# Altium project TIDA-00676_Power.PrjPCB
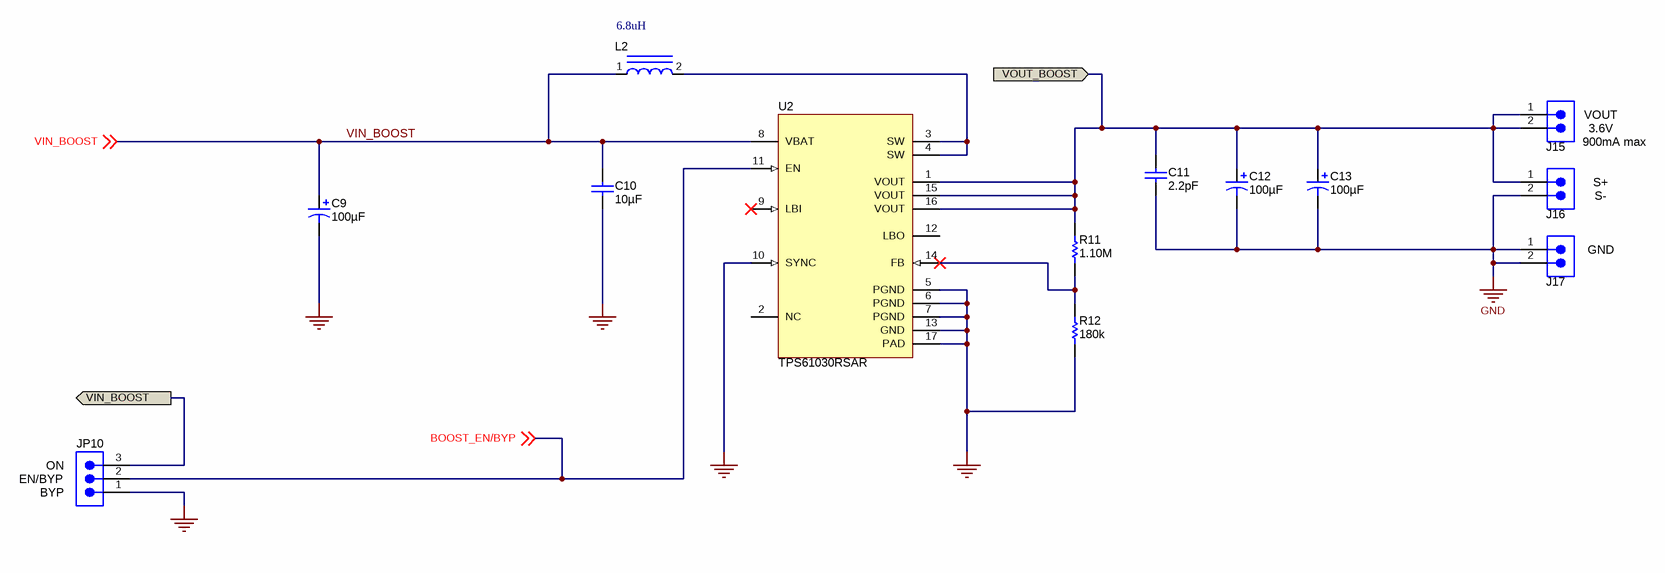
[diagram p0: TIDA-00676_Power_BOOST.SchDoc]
CopyrightYear: 2015; PCB_Layout: Fred Illguth; PCB_Rev: E1; PRJ_Customer: Public Release; PRJ_Engineer: Florian Feckl; PRJ_Number: ALPS-0199; PRJ_Title: TIDA-00676; SCH_Rev: E1; TechSupport: http://www.ti.com/support
3 sheets, 89 parts. Net scope: flat (ports and power ports of the same name join across sheets).
Board file: TIDA-00676_Power.PcbDoc
Sheets:
  TIDA-00676_Power_BOOST.SchDoc
  TIDA-00676_Power_BUCK.SchDoc
  TIDA-00676_Power_Hardware.SchDoc

## Sheet TIDA-00676_Power_BOOST.SchDoc
size 431 x 279 mm; Date: Not shown in title block; ApprovedBy: Not shown in title block; CheckedBy: Not shown in title block; Author: Not shown in title block; CompanyName: Not shown in title block; Engineer: Not shown in title block; Organization: Not shown in title block; Address1: Not shown in title block; Address2: Not shown in title block; Address3: Not shown in title block; Address4: Not shown in title block; DocumentNumber: 1; Revision: Use project parameter SCH_Rev; SheetNumber: 1; SheetTotal: 1; PageSetup: Record=PageOptions|CenterHorizontal=True|CenterVertical=True|PrintScale=1.00|XCorrection=1.00|YCorrection=1.00|PrintKind=0|BorderSize=5000000|LeftOffset=0|BottomOffset=0|Orientation=2|PaperLength=1000|PaperWidth=1000|Scale=100|PaperSource=15|PrintQuality=600|MediaType=1|DitherType=10|PaperKind=Letter|PrintScaleMode=1

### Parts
C9  ValueDisplayed: 100µF  [CC_CASED]  (hidden comment: 594D107X0016D2T)
C10  ValueDisplayed: 10µF  [1206]  (hidden comment: C3216X5R0J106M)
C11  ValueDisplayed: 2.2pF  [0805_HV]  (hidden comment: 08055A2R2CAT2A)
C12  ValueDisplayed: 100µF  [CC_CASED]  (hidden comment: 594D107X0016D2T)
C13  ValueDisplayed: 100µF  [CC_CASED]  (hidden comment: 594D107X0016D2T)
J15  TSW-102-07-G-S  [TSW-102-07-G-S]  (value not drawn)
J16  TSW-102-07-G-S  [TSW-102-07-G-S]  (value not drawn)
J17  TSW-102-07-G-S  [TSW-102-07-G-S]  (value not drawn)
JP10  TSW-103-07-G-S  [TSW-103-07-G-S]  (value not drawn)
L2  value 6.8uH  [IND_CDRH124]  (hidden comment: CDRH124-6R8)
R11  ValueDisplayed: 1.10M  [0603]  (hidden comment: CRCW06031M10FKEA)
R12  ValueDisplayed: 180k  [0603]  (hidden comment: CRCW0603180KJNEA)
U2  TPS61030RSAR  [RSA0016B]

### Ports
VIN_BOOST, VOUT_BOOST

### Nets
GND: C9.2(-) C10.2 C11.2 C12.2(-) C13.2(-) J16.2 J17.1 J17.2 JP10.1 R12.1 U2.5(PGND) U2.6(PGND) U2.7(PGND) U2.10(SYNC) U2.13(GND) U2.17(PAD)
BOOST_EN/BYP: JP10.2 U2.11(EN) ; off-sheet BOOST_EN/BYP
VIN_BOOST: JP10.3 ; port VIN_BOOST
VIN_BOOST: C9.1(+) C10.1 L2.1 U2.8(VBAT) ; off-sheet VIN_BOOST  [a separate net that carries the same name]
VOUT_BOOST: C11.1 C12.1(+) C13.1(+) J15.1 J15.2 J16.1 R11.2 U2.1(VOUT) U2.15(VOUT) U2.16(VOUT) ; port VOUT_BOOST
NetL2_2: L2.2 U2.3(SW) U2.4(SW)
NetR11_1: R11.1 R12.2 U2.14(FB)

Not connected (* = marked no-connect by the designer): U2 2(NC) 9(LBI)* 12(LBO)

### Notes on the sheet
- (near J15) VOUT
- 3.6V
- 900mA max
- S+
- S-
- GND
- (near JP10) EN/BYP
- (near JP10) BYP
- (near JP10) ON

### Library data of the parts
C9 C12 C13 = 594D107X0016D2T: CAP, TA, 100 µF, 16 V, +/- 20%, 0.09 ohm, SMD; Manufacturer: Vishay-Sprague; Polarized: Y; CompType: Capacitor; Value: 100uF; U/M: EA; Cap_F: 0.0001; Tolerance_%: 20; VDC_V: 16; Value2: 16V; ESR_ohm: 0.09; IRMS_A: 1.3; TaMin_C: -55; TaMax_C: 85; Cap_Case: D
C10 = C3216X5R0J106M: CAP, CERM, 10 µF, 6.3 V, +/- 20%, X5R, 1206; Manufacturer: TDK; Polarized: N; CompType: Capacitor; Value: 10uF; U/M: EA; Cap_F: 0.00001; Tolerance_%: 20; ESR_ohm: 0.0031; Value1: 0.0031 ohm; VDC_V: 6.3; Value2: 6.3V; IRMS_A: 4.1; TaMin_C: -55; TaMax_C: 85
C11 = 08055A2R2CAT2A: CAP, CERM, 2.2 pF, 50 V, +/- 11%, C0G/NP0, 0805; Manufacturer: AVX; Polarized: N; CompType: Capacitor; Value: 2.2pF; U/M: EA; Cap_F: 0.0000000000022; Tolerance_%: 11; ESR_ohm: 4.726; Value1: 4.726 ohm; VDC_V: 50; Value2: 50V; TaMin_C: -55; TaMax_C: 125; Cap_Case: 0805
J15-J17 = TSW-102-07-G-S: Header, TH, 100mil, 2x1, Gold plated, 230 mil above insulator; Manufacturer: Samtec, Inc.; SymbolCreator: a0412235; U/M: EA
JP10 = TSW-103-07-G-S: Header, TH, 100mil, 3x1, Gold plated, 230 mil above insulator; Manufacturer: Samtec, Inc.; SymbolCreator: a0799628; U/M: EA
L2 = IND_CDRH124_SERIES: Inductor, SMT, yyA, zzmilliohm; Manufacturer: Sumida; Area: 95275
R11 = CRCW06031M10FKEA: RES, 1.10 M, 1%, 0.1 W, 0603; Manufacturer: Vishay-Dale; CompType: Resistor; Value: 1.10Meg; Res_ohm: 1100000; Value_Code: 1M10; Tolerance_%: 1; Power_W: 0.1; Value2: 0.1W; VDC_V: 75; TempCo: 100 ppm/C; EIA_Code: E96; U/M: EA
R12 = CRCW0603180KJNEA: RES, 180 k, 5%, 0.1 W, 0603; Manufacturer: Vishay-Dale; CompType: Resistor; Value: 180k; Res_ohm: 180000; Tolerance_%: 5; Power_W: 0.1; Value2: 0.1W; VDC_V: 75; TempCo: 200 ppm/C; EIA_Code: E24; U/M: EA
U2 = TPS61030RSAR: 96% Efficient Synchronous Boost Converter With 4A Switch, RSA0016B; Manufacturer: Texas Instruments; SymbolCreator: Altium; CompType: IC; U/M: EA

## Sheet TIDA-00676_Power_BUCK.SchDoc
size 431 x 279 mm; Date: Not shown in title block; ApprovedBy: Not shown in title block; CheckedBy: Not shown in title block; Author: Not shown in title block; CompanyName: Not shown in title block; Engineer: Not shown in title block; Organization: Not shown in title block; Address1: Not shown in title block; Address2: Not shown in title block; Address3: Not shown in title block; Address4: Not shown in title block; DocumentNumber: 1; Revision: Use project parameter SCH_Rev; SheetNumber: 1; SheetTotal: 2; PageSetup: Record=PageOptions¦CenterHorizontal=True¦CenterVertical=True¦PrintScale=0.62¦XCorrection=1.00¦YCorrection=1.00¦PrintKind=0¦BorderSize=5000000¦LeftOffset=0¦BottomOffset=0¦Orientation=2¦PaperLength=1000¦PaperWidth=1000¦Scale=100¦PaperSource=15¦PrintQuality=600¦MediaType=1¦DitherType=10¦PaperKind=Letter¦PrintScaleMode=1
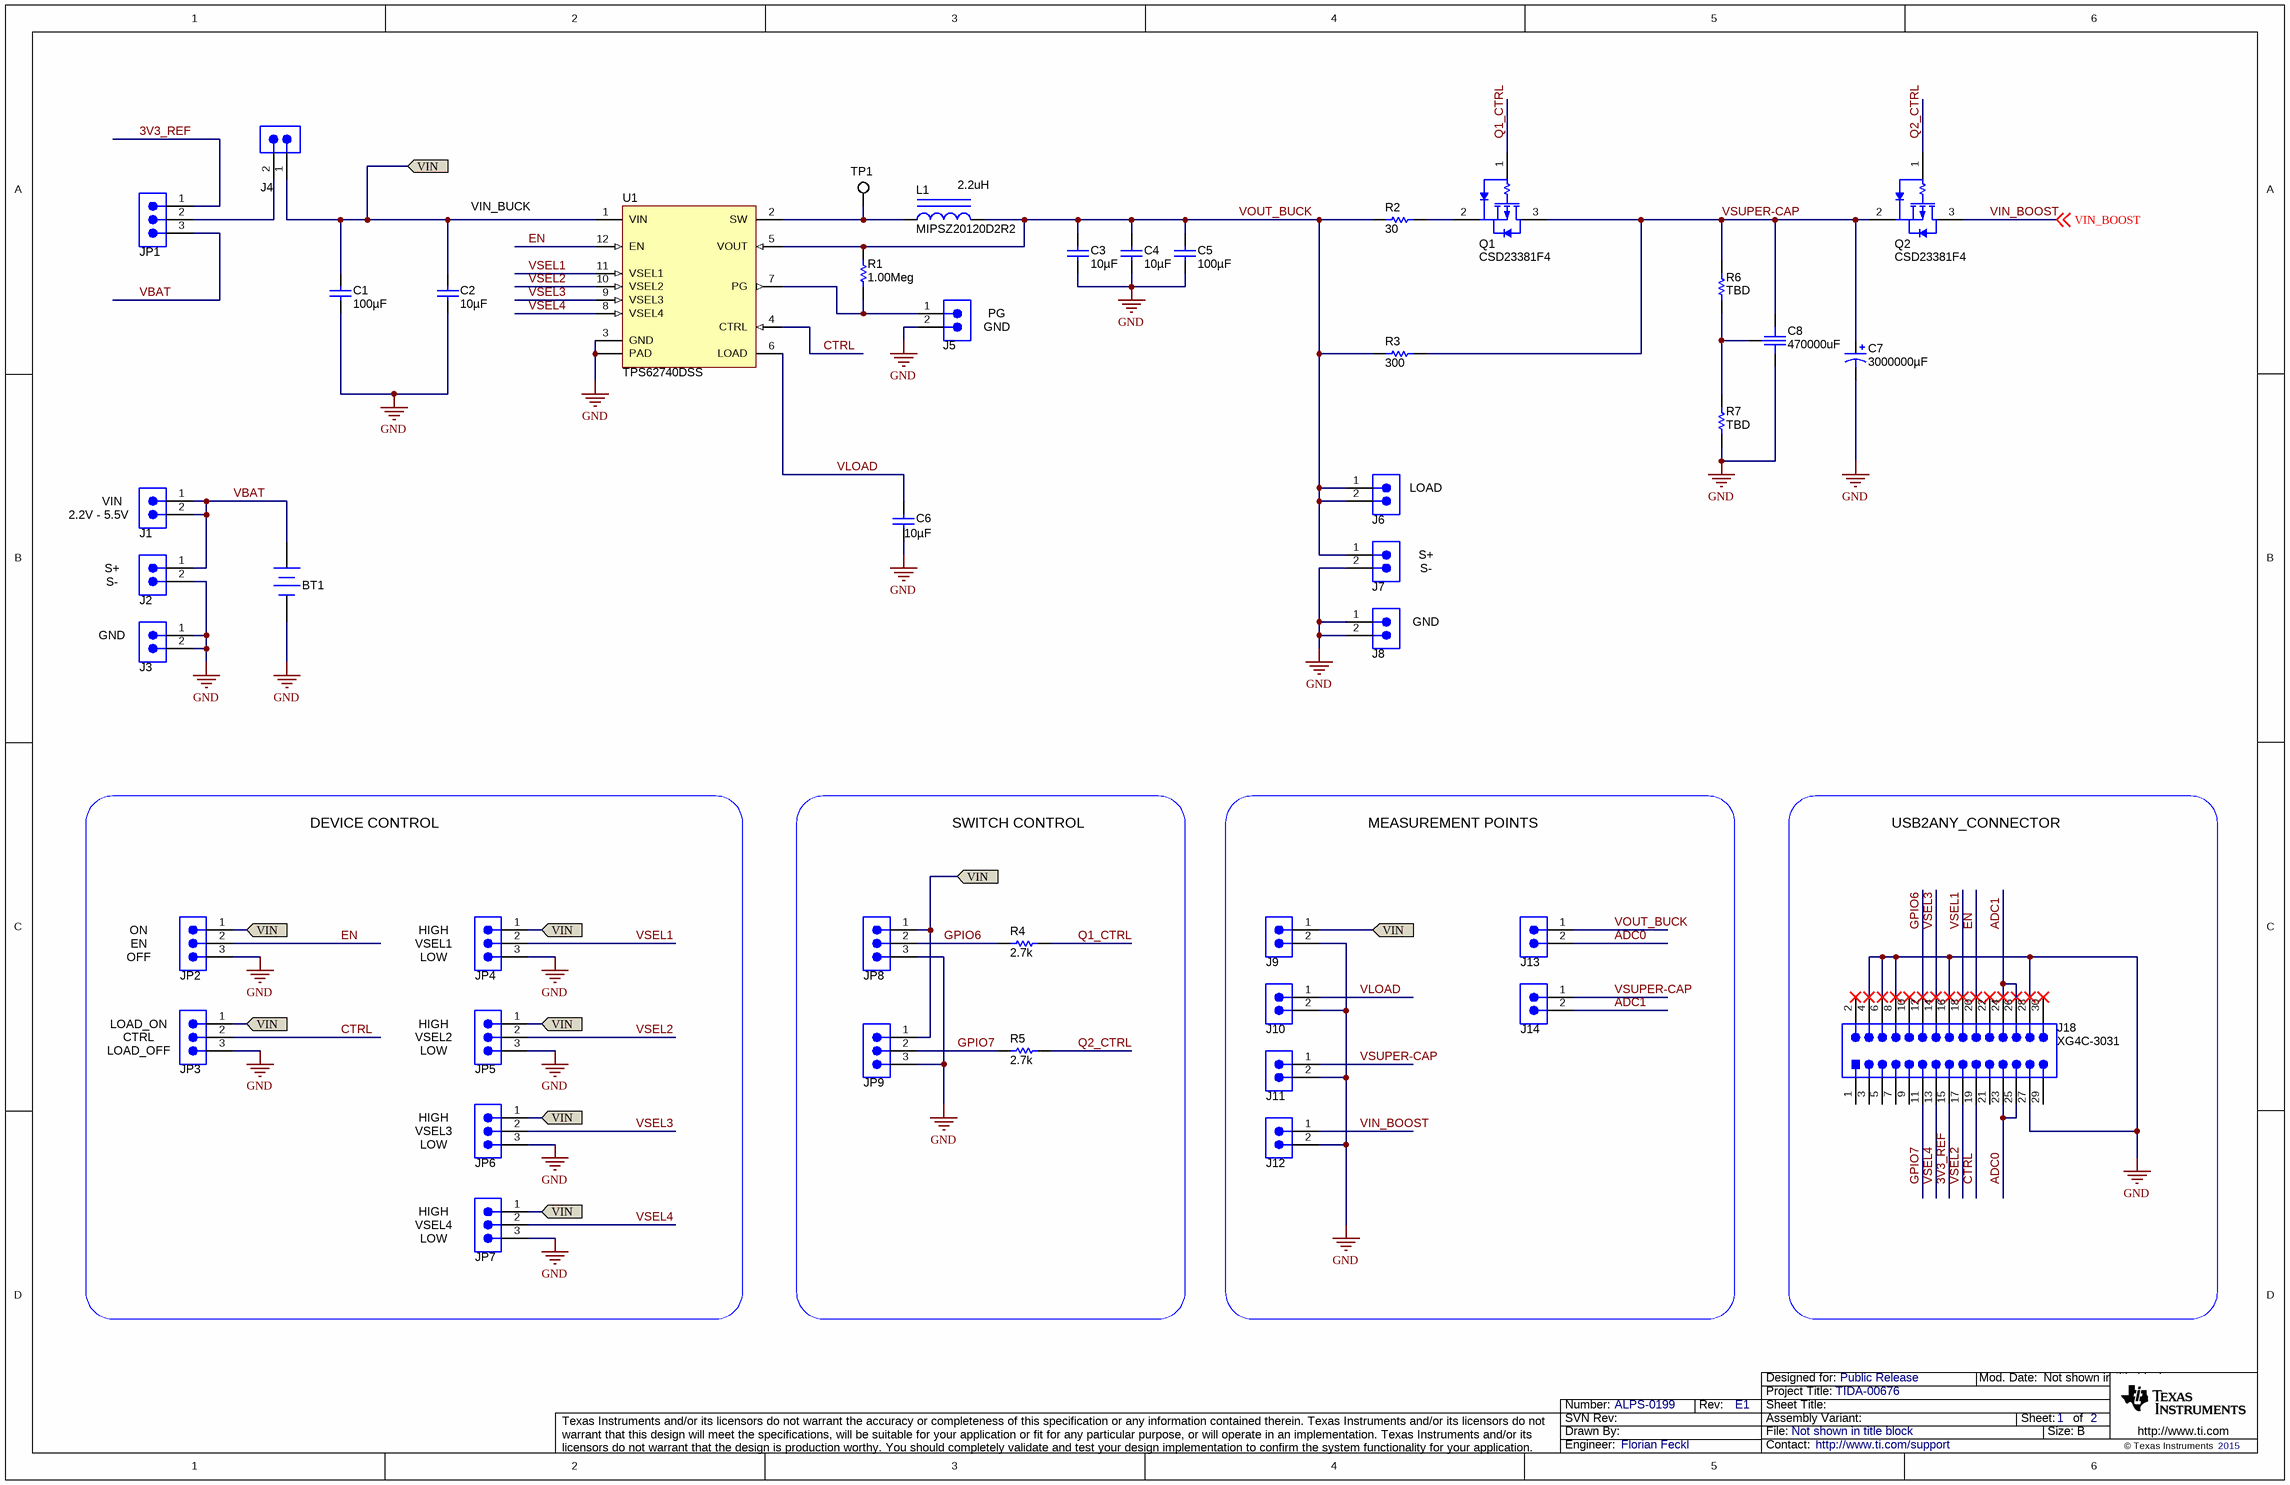
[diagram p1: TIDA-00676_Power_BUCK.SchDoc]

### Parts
BT1  SL360/P  [Tadiran_SL360-P]  (value not drawn)
C1  ValueDisplayed: 100µF  [1210]  (hidden comment: GRM32ER60J107ME20L)
C2  ValueDisplayed: 10µF  [0603_HV]  (hidden comment: GRM188R60J106ME84)
C3  ValueDisplayed: 10µF  [0603_HV]  (hidden comment: GRM188R60J106ME84)
C4  ValueDisplayed: 10µF  [0603]  (hidden comment: GRM188R60J106ME84)
C5  ValueDisplayed: 100µF  [1210]  (hidden comment: GRM32ER60J107ME20L)
C6  ValueDisplayed: 10µF  [0603]  (hidden comment: GRM188R60J106ME84)
C7  ValueDisplayed: 3000000µF  [ESHSR_800x2000]  (hidden comment: ESHSR-0003C0-002R7)
C8  ValueDisplayed: 470000uF  [DMF_2100x1400]  (hidden comment: DMF3Z5R5H474M3DTA0)
J1  TSW-102-07-G-S  [TSW-102-07-G-S]  (value not drawn)
J2  TSW-102-07-G-S  [TSW-102-07-G-S]  (value not drawn)
J3  TSW-102-07-G-S  [TSW-102-07-G-S]  (value not drawn)
J4  TSW-102-07-G-S  [TSW-102-07-G-S]  (value not drawn)
J5  TSW-102-07-G-S  [TSW-102-07-G-S]  (value not drawn)
J6  TSW-102-07-G-S  [TSW-102-07-G-S]  (value not drawn)
J7  TSW-102-07-G-S  [TSW-102-07-G-S]  (value not drawn)
J8  TSW-102-07-G-S  [TSW-102-07-G-S]  (value not drawn)
J9  TSW-102-07-G-S  [TSW-102-07-G-S]  (value not drawn)
J10  TSW-102-07-G-S  [TSW-102-07-G-S]  (value not drawn)
J11  TSW-102-07-G-S  [TSW-102-07-G-S]  (value not drawn)
J12  TSW-102-07-G-S  [TSW-102-07-G-S]  (value not drawn)
J13  TSW-102-07-G-S  [TSW-102-07-G-S]  (value not drawn)
J14  TSW-102-07-G-S  [TSW-102-07-G-S]  (value not drawn)
J18  XG4C-3031  [OMRON_XG4C-3031]
JP1  TSW-103-07-G-S  [TSW-103-07-G-S]  (value not drawn)
JP2  TSW-103-07-G-S  [TSW-103-07-G-S]  (value not drawn)
JP3  TSW-103-07-G-S  [TSW-103-07-G-S]  (value not drawn)
JP4  TSW-103-07-G-S  [TSW-103-07-G-S]  (value not drawn)
JP5  TSW-103-07-G-S  [TSW-103-07-G-S]  (value not drawn)
JP6  TSW-103-07-G-S  [TSW-103-07-G-S]  (value not drawn)
JP7  TSW-103-07-G-S  [TSW-103-07-G-S]  (value not drawn)
JP8  TSW-103-07-G-S  [TSW-103-07-G-S]  (value not drawn)
JP9  TSW-103-07-G-S  [TSW-103-07-G-S]  (value not drawn)
L1  MIPSZ20120D2R2  value 2.2uH  [MIPSZ20120D]
Q1  CSD23381F4  [YJC0003A]
Q2  CSD23381F4  [YJC0003A]
R1  value 1.00Meg  [0603]  (hidden comment: RC0603FR-071ML)
R2  value 30  [0603]  (hidden comment: CRCW060330R0JNEA)
R3  value 300  [0603]  (hidden comment: RC0603FR-07300RL)
R4  value 2.7k  [0603]  (hidden comment: CRCW06032K70JNEA)
R5  value 2.7k  [0603]  (hidden comment: CRCW06032K70JNEA)
R6  value TBD  [0603]  (hidden comment: Used in BOM report)
R7  value TBD  [0603]  (hidden comment: Used in BOM report)
TP1  5002  [Keystone5002]  (value not drawn)
U1  TPS62740DSS  [DSS0012A]

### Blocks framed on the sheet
DEVICE CONTROL: JP2-JP7
SWITCH CONTROL: JP8 JP9 R4 R5
MEASUREMENT POINTS: J9-J14
USB2ANY_CONNECTOR: J18

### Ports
VIN

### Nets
GND: BT1.2(-) C1.2 C2.2 C3.2 C4.2 C5.2 C6.2 C7.2(-) C8.2 J2.2 J3.1 J3.2 J5.2 J7.2 J8.1 J8.2 J9.2 J10.2 J11.2 J12.2 J18.4 J18.6 J18.8 J18.16 J18.27 J18.28 JP2.3 JP3.3 JP4.3 JP5.3 JP6.3 JP7.3 JP8.3 JP9.3 R7.1 U1.3(GND) U1.13(PAD)
3V3_REF: J18.15 JP1.1
ADC0: J13.2 J18.23 J18.25
ADC1: J14.2 J18.24 J18.26
CTRL: J18.19 JP3.2 U1.4(CTRL)
EN: J18.20 JP2.2 U1.12(EN)
GPIO6: J18.12 JP8.2 R4.1
GPIO7: J18.11 JP9.2 R5.1
Q1_CTRL: Q1.1(G) R4.2
Q2_CTRL: Q2.1(G) R5.2
VBAT: BT1.1(+) J1.1 J1.2 J2.1 JP1.3
VIN: C1.1 C2.1 J4.1 J9.1 JP2.1 JP3.1 JP4.1 JP5.1 JP6.1 JP7.1 JP8.1 JP9.1 U1.1(VIN) ; port VIN
VIN_BOOST: J12.1 Q2.3(D) ; off-sheet VIN_BOOST
VLOAD: C6.1 J10.1 U1.6(LOAD)
VOUT_BUCK: C3.1 C4.1 C5.1 J6.1 J6.2 J7.1 J13.1 L1.2 R1.2 R2.1 R3.1 U1.5(VOUT)
VSEL1: J18.18 JP4.2 U1.11(VSEL1)
VSEL2: J18.17 JP5.2 U1.10(VSEL2)
VSEL3: J18.14 JP6.2 U1.9(VSEL3)
VSEL4: J18.13 JP7.2 U1.8(VSEL4)
VSUPER-CAP: C7.1(+) C8.1 J11.1 J14.1 Q1.3(D) Q2.2(S) R3.2 R6.2
NetC8_3: C8.3 R6.1 R7.2
NetJ4_2: J4.2 JP1.2
NetJ5_1: J5.1 R1.1 U1.7(PG)
NetL1_1: L1.1 TP1.1 U1.2(SW)
NetQ1_2: Q1.2(S) R2.2

Not connected (* = marked no-connect by the designer): J18 1 2* 3 5 7 9 10* 21 22* 29 30*

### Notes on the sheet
- VIN_BUCK
- (near J5) PG
- (near J5) GND
- (near J1) VIN
- (near J6) LOAD
- (near J1) 2.2V - 5.5V
- S+
- S-
- GND
- ON
- EN
- OFF
- HIGH
- (near JP4) VSEL1
- LOW
- (near JP3) LOAD_ON
- CTRL
- (near JP5) VSEL2
- (near JP3) LOAD_OFF
- (near JP6) VSEL3
- (near JP7) VSEL4

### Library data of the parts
BT1 = SL360/P: Battery, 3.6 V, 2.4 Ah, Axial, TH; Manufacturer: Tadiran Batteries; Value: 3.6V
C1 C5 = GRM32ER60J107ME20L: CAP, CERM, 100uF, 6.3V, +/-20%, X5R, 1210; Manufacturer: MuRata; Polarized: N; CompType: Capacitor; U/M: EA; Cap_F: 0.0001; Tolerance_%: 20; ESR_Ohm: 0.002; Value1: 0.002 ohm; VDC_V: 6.3; TaMin_C: -55; TaMax_C: 85
C2 C3 = GRM188R60J106ME84: CAP, CERM, 10uF, 6.3V, +/-20%, X5R, 0603; Manufacturer: MuRata; Polarized: N; CompType: Capacitor; U/M: EA; Cap_F: 0.00001; Tolerance_%: 20; Value1: Unknown; VDC_V: 6.3; TaMin_C: -55; TaMax_C: 85; Cap_Case: 0603
C4 C6 = GRM188R60J106ME84: CAP, CERM, 10uF, 6.3V, +/-20%, X5R, 0603; Manufacturer: MuRata; Polarized: N; CompType: Capacitor; U/M: EA; Cap_F: 0.00001; Tolerance_%: 20; Value1: Unknown; VDC_V: 6.3; TaMin_C: -55; TaMax_C: 85
C7 = ESHSR-0003C0-002R7: CAP, Electric Double Layer, 3000000uF, 2.7V, +20/-10%, 0.061 ohm, TH; Manufacturer: NESSCAP; Polarized: Y; CompType: Capacitor; U/M: EA; Cap_F: 3; Tolerance_%: 20; VDC_V: 2.7; ESR_Ohm: 0.061; TaMin_C: -40; TaMax_C: 65; Cap_Case: 8x20mm
C8 = DMF3Z5R5H474M3DTA0: CAP, Electric Double Layer, 470000uF, 4.2 V, +/- 20%, 0.045 ohm, Electrical  Double Layer Capacitor, Body 21.5x14.5mm, Pitch 3.5mm SMD; Manufacturer: MuRata; SymbolCreator: a0411947; U/M: EA; Cap_F: 0.47; Tolerance_%: 20; VDC_V: 4.2; Value2: 4.2V; ESR_ohm: 0.045; TaMin_C: -30; TaMax_C: 70; Polarized: Y; Cap_Case: 21x14mm
J1-J14 = TSW-102-07-G-S: as J15 on sheet TIDA-00676_Power_BOOST
J18 = XG4C-3031: Connector, 15x2, 3A 300V STRT DIP, TH; Manufacturer: Omron Electronic Components; SymbolCreator: a0412235; U/M: EA
JP1-JP9 = TSW-103-07-G-S: as JP10 on sheet TIDA-00676_Power_BOOST
L1 = MIPSZ20120D2R2: Inductor, Multilayer, Ceramic, 2.2uH, 0.7A, 0.23 ohm, SMD; Manufacturer: FDK; Ind_H: 2.2E-6; ValueDisplayed: 2.2µH; Imax_A: 0.7; Irms: 0.7A @ C rise; DCR_ohm: 0.23
Q1 Q2 = CSD23381F4: MOSFET, P-CH, -12V, -2.3A, 1.0x0.35x0.6mm; Manufacturer: Texas Instruments; Alternate Manufacturer: None; SymbolCreator: a0411947; U/M: EA; ChType: P; VdsMax_V: -12; Value1: 0.15 ohm; Rdson45_Ohm: 0.15; Value2: 1.14 nC; QgTyp_nC: 1.14; Vgs_V: 8; IdsMax_A: -2.3
R1 = RC0603FR-071ML: RES, 1.00Meg ohm, 1%, 0.1W, 0603; Manufacturer: Yageo America; CompType: Resistor; Res_ohm: 1000000; Value_Code: 1M00; Tolerance_%: 1; Power_W: 0.1; VDC_V: 150; TempCo: 200 ppm/C; EIA_Code: E96; U/M: EA
R2 = CRCW060330R0JNEA: RES, 30 ohm, 5%, 0.1W, 0603; Manufacturer: Vishay-Dale; CompType: Resistor; Value_Code: 30R0; Tolerance_%: 5; Power_W: 0.1; VDC_V: 75; TempCo: 200 ppm/C; EIA_Code: E24; U/M: EA
R3 = RC0603FR-07300RL: RES, 300 ohm, 1%, 0.1W, 0603; Manufacturer: Yageo America; CompType: Resistor; Value_Code: 300R; Tolerance_%: 1; Power_W: 0.1; VDC_V: 150; TempCo: 200 ppm/C; U/M: EA
R4 R5 = CRCW06032K70JNEA: RES, 2.7k ohm, 5%, 0.1W, 0603; Manufacturer: Vishay-Dale; CompType: Resistor; Res_ohm: 2700; Value_Code: 2k70; Tolerance_%: 5; Power_W: 0.1; VDC_V: 75; TempCo: 200 ppm/C; EIA_Code: E24; U/M: EA
R6 R7 = Resistor: RES, xxx ohm, x%, xW, [PackageReference]; U/M: EA
TP1 = 5002: Test Point, Miniature, White, TH; Manufacturer: Keystone; CompType: Test Point Loop; U/M: EA
U1 = TPS62740DSS: 360nA IQ Step Down Converter for Low Power Applications, DSS0012A; Alternate Manufacturer: None; Manufacturer: Texas Instruments; SymbolCreator: a0411947; CompType: IC; U/M: EA

## Sheet TIDA-00676_Power_Hardware.SchDoc: Hardware
size 431 x 279 mm; Date: Not shown in title block; ApprovedBy: Not shown in title block; CheckedBy: Not shown in title block; Author: Not shown in title block; CompanyName: Not shown in title block; Engineer: Not shown in title block; Organization: Not shown in title block; Address1: Not shown in title block; Address2: Not shown in title block; Address3: Not shown in title block; Address4: Not shown in title block; DocumentNumber: 2; Revision: Use project parameter SCH_Rev; SheetNumber: 2; SheetTotal: 2; PageSetup: Record=PageOptions¦CenterHorizontal=True¦CenterVertical=True¦PrintScale=1.00¦XCorrection=1.00¦YCorrection=1.00¦PrintKind=0¦BorderSize=5000000¦LeftOffset=0¦BottomOffset=0¦Orientation=2¦PaperLength=1000¦PaperWidth=1000¦Scale=100¦PaperSource=15¦PrintQuality=600¦MediaType=1¦DitherType=10¦PaperKind=Letter¦PrintScaleMode=1
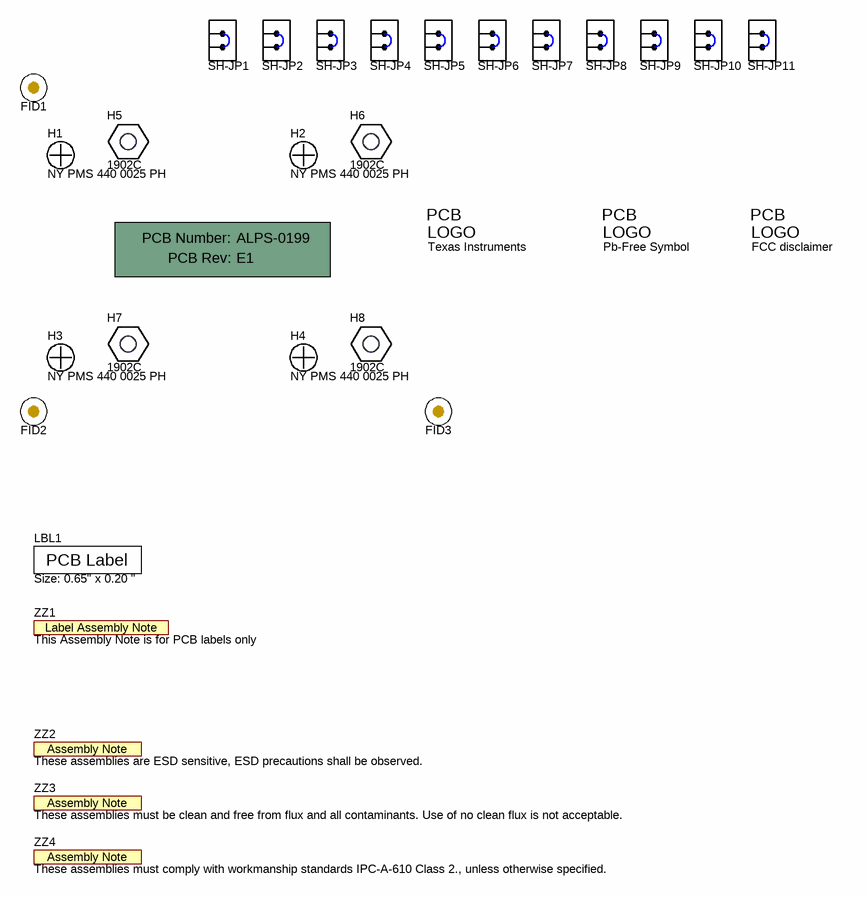
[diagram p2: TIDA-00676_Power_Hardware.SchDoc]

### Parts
!PCB  Printed Circuit Board  (value not drawn)  (mechanical)
FID1  Fiducial  [Fiducial10-20]  (value not drawn)
FID2  Fiducial  [Fiducial10-20]  (value not drawn)
FID3  Fiducial  [Fiducial10-20]  (value not drawn)
H1  NY PMS 440 0025 PH  [NY PMS 440 0025 PH]
H2  NY PMS 440 0025 PH  [NY PMS 440 0025 PH]
H3  NY PMS 440 0025 PH  [NY PMS 440 0025 PH]
H4  NY PMS 440 0025 PH  [NY PMS 440 0025 PH]
H5  1902C  [Keystone_1902C]
H6  1902C  [Keystone_1902C]
H7  1902C  [Keystone_1902C]
H8  1902C  [Keystone_1902C]
LBL1  Size: 0.65" x 0.20 "  [Label_650x200]
Logo1  Texas Instruments  [TI_Stacked_Overlay_Small]  (no BOM)
Logo2  Pb-Free Symbol  [Pb-Free_Overlay_Medium]  (no BOM)
Logo3  FCC disclaimer  [FCC_disclaimer]  (no BOM)
SH-JP1  969102-0000-DA  [SNT-100-BK-G]  (value not drawn)
SH-JP2  969102-0000-DA  [SNT-100-BK-G]  (value not drawn)
SH-JP3  969102-0000-DA  [SNT-100-BK-G]  (value not drawn)
SH-JP4  969102-0000-DA  [SNT-100-BK-G]  (value not drawn)
SH-JP5  969102-0000-DA  [SNT-100-BK-G]  (value not drawn)
SH-JP6  969102-0000-DA  [SNT-100-BK-G]  (value not drawn)
SH-JP7  969102-0000-DA  [SNT-100-BK-G]  (value not drawn)
SH-JP8  969102-0000-DA  [SNT-100-BK-G]  (value not drawn)
SH-JP9  969102-0000-DA  [SNT-100-BK-G]  (value not drawn)
SH-JP10  969102-0000-DA  [SNT-100-BK-G]  (value not drawn)
SH-JP11  969102-0000-DA  [SNT-100-BK-G]  (value not drawn)
ZZ1  This Assembly Note is for PCB labels only  [AssemblyNoteLabel]  (no BOM)
ZZ2  These assemblies are ESD sensitive, ESD precautions shall be observed.  [AssemblyNote]  (no BOM)
ZZ3  These assemblies must be clean and free from flux and all contaminants. Use of no clean flux is not acceptable.  [AssemblyNote]  (no BOM)
ZZ4  These assemblies must comply with workmanship standards IPC-A-610 Class 2., unless otherwise specified.  [AssemblyNote]  (no BOM)

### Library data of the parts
!PCB = PCB: Manufacturer: Any; SymbolCreator: a0412235
FID1-FID3 = Fiducial: Fiducial mark.  There is nothing to buy or mount.; SymbolCreator: codlsc
H1-H4 = NY PMS 440 0025 PH: Machine Screw, Round, #4-40 x 1/4, Nylon, Philips panhead; Manufacturer: B&F Fastener Supply; CompType: Hardware; SymbolCreator: codlsc; U/M: EA
H5-H8 = 1902C: Standoff, Hex, 0.5"L #4-40 Nylon; Manufacturer: Keystone; CompType: Hardware
LBL1 = THT-14-423-10: Thermal Transfer Printable Labels, 0.650" W x 0.200" H - 10,000 per roll; Manufacturer: Brady; SymbolCreator: a0412235; CompType: Label
Logo1 = TI_Logo: Texas Instrument Corporate Signature; SymbolCreator: codlsc
Logo2 = Pb-Free: SymbolCreator: a0412235
Logo3 = FCC_disclaimer: SymbolCreator: codlsc
SH-JP1-SH-JP11 = 969102-0000-DA: Shunt, 100mil, Gold plated, Black; Manufacturer: 3M; Alternate Manufacturer: Samtec; Value: 1x2; Note: You can "mate" this to a header by matching the designator.  i.e. use SH-J3 for header J3
ZZ1 = AssemblyNoteLabel: SymbolCreator: a0412235
ZZ2-ZZ4 = AssemblyNote: SymbolCreator: codlsc

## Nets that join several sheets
GND: TIDA-00676_Power_BOOST (16 pins), TIDA-00676_Power_BUCK (37 pins)
VIN_BOOST: TIDA-00676_Power_BOOST (C9.1 C10.1 L2.1 U2.8), TIDA-00676_Power_BUCK (J12.1 Q2.3)

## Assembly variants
001: not fitted BT1 C5 C6 C8 FID1 FID2 FID3 H1 H2 H3 H4 H5 H6 H7 H8 LBL1 R6 R7 SH-JP1 SH-JP2 SH-JP3 SH-JP4 SH-JP5 SH-JP6 SH-JP7 SH-JP8 SH-JP9 SH-JP10 SH-JP11 TP1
